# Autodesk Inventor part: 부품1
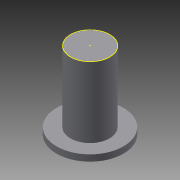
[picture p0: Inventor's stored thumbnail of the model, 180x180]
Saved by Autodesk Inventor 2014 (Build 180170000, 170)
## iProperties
Created: 2017-05
Part Number: 부품1
Material: Generic
Document SubType Name: Modeling
Designer: Administrator
Density: 1 g/cm^3
Appearance: Default
Author: Administrator
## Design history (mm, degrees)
sketch "스케치1"
  geometry: C1 r 53 at (0, 0); 1 further point
  constraints: 1 centre point, 1 coincident
  dimensions: "d0" = 106 diameter of C1
extrude "돌출1" new body sketch "스케치1" distance "d1" = 10; taper "d2" = 0 deg
sketch "스케치2"
  geometry: C1 r 53 at (0, 0) reference; C2 r 31 at (0, 0)
  constraints: 1 centre point, 1 coincident
  dimensions: "d3" = 62 diameter of C2
extrude "돌출2" join sketch "스케치2" distance "d4" = 112; taper "d5" = 0 deg
sketch "스케치3"
  geometry: C1 r 31 at (0, 0) reference
node "솔리드1"
